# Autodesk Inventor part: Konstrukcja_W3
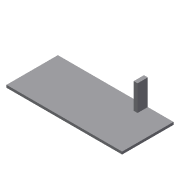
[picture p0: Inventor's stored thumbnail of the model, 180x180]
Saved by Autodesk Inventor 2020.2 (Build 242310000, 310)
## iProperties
Created: 2014-09
Part Number: Konstrukcja_W3
Material: Ogólny
Document SubType Name: Modeling
Designer: F.Stasiak
Density: 1 g/cm^3
Appearance: Domyślna
Catalog Web Link: www.expertbooks.pl
Manager: www.cadconsulting.pl
Company: Fabian Stasiak CAD Consulting
Author: F.Stasiak
Subject: Zbiór ćwiczeń. Autodesk Inventor 2020. Kurs Professional
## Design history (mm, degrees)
sketch "Szkic1"
  geometry: L1 (-175, 100)-(175, 100); L2 (175, 100)-(175, -100); L3 (175, -100)-(-175, -100); L4 (-175, -100)-(-175, 100); L5 (-175, 100)-(175, -100); L6 (175, 100)-(-175, -100); 1 further point
  constraints: 12 end point, 2 midpoint, 2 parallel, 1 horizontal, 1 perpendicular
  dimensions: "d0" = 350 distance of L2.end L3.end; "d1" = 200 distance of L1.end L2.end
extrude "Wyciągnięcie proste1" new body sketch "Szkic1" distance "d2" = 10; taper "d3" = 0 deg
sketch "Szkic2"
  geometry: L1 (175, 100)-(-175, 100) reference; L2 (-175, 100)-(-175, -100) reference; L3 (-175, -100)-(175, -100) reference; L4 (175, -100)-(175, 100) reference; L5 (175, 100)-(160, 100); L6 (160, 100)-(160, 60); L7 (160, 60)-(175, 60); L8 (175, 60)-(175, 100); 1 further point
  constraints: 8 end point, 2 parallel, 1 horizontal, 1 perpendicular
  dimensions: "d4" = 15 distance of L7.end L6.end; "d5" = 40 distance of L6.end L5.end
extrude "Wyciągnięcie proste2" join sketch "Szkic2" distance "d6" = 100; taper "d7" = 0 deg
sketch "Szkic3"
  geometry: L1 (0, 200)-(0, 0) reference; L2 (0, 200)-(-110, 200) reference; L3 (-110, 160)-(-110, 200) reference; L4 (-10, 160)-(-110, 160) reference; L5 (-10, 0)-(-10, 160) reference; L6 (0, 0)-(-10, 0) reference; L7 (-10, 160)-(-10, 200); L8 (0, 200)-(-110, 200) reference; 1 further point
  constraints: 2 end point, 1 point on line, 1 vertical
extrude "Wyciągnięcie proste3" join sketch "Szkic3" distance "d8" = 100; taper "d9" = 0 deg
node "Bryła1"
node "Pętla rzutowana1"
node "Pętla rzutowana2"
